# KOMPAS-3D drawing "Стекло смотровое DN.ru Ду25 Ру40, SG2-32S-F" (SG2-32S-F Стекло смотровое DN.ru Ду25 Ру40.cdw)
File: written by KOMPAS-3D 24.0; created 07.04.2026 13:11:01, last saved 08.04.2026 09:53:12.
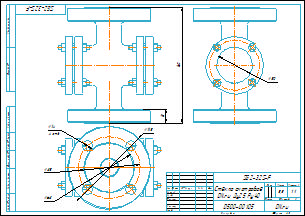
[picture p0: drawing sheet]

Document properties: Автор: Main; Форматы листов документа: A3; Полное имя файла: SG2-32S-F Стекло смотровое DN.ru Ду25 Ру40.m3d; Масса: 5.5; Наименование: Стекло смотровое DN.ru Ду25 Ру40; Количество листов документа: 1; Примечание: D500-00105

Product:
- Body: Тело 1  | qty 1
    Масса: 4.394636
- Part/product: Стекло смотровое DN.ru Ду25 Ру40  | designation SG2-32S-F
    Масса: 5.5
    Раздел спецификации: Прочие изделия
    Примечание: D500-00105

Views: Вид 1, Снизу, Проекционный вид 2
Referenced files in D:\DN.ru Аутсерс\Стекло смотровое DN.ru\Стекло смотровое DN.ru SG2-34G-F тип В ГОСТ 21836-2021 Ду100 Ру16, углеродистая сталь, фланцевое\: SG2-34G-F тип В Стекло смотровое DN.ru Ду100 Ру16.m3d, SG2-34G-F тип ВСтекло смотровое DN.ru Ду100 Ру16.cdw
Referenced files in D:\DN.ru Аутсерс\Стекло смотровое DN.ru\SG2-32S-F Стекло смотровое DN.ru Ду25 Ру40\: SG2-32S-F Стекло смотровое DN.ru Ду25 Ру40.m3d
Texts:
  SG2-32S-F
  Стекло смотровое
  DN.ru Ду25 Ру40
  Стекло смотровое DN.ru Ду25 Ру40
  SG2-32S-F Стекло смотровое DN.ru Ду25 Ру40
Dimensions and other numbers on the sheet: 0; 3; 2; 4; 160; 18; 14; 4 отв.; 85; 115; 68; 1:1; 1; 5,5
